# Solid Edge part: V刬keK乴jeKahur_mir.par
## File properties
Last saved by: Egon 815
Revision: 52
Accuracy: 0,990
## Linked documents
ljeKahur.par
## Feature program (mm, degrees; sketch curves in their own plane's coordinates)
part copy "CopiedPart_1"
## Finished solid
Body 1: solid body, 18 faces, 34 edges, 18 vertices.
  Faces by surface: plane 11, cone 3, cylinder 2, spline 2
  Edges by curve: line 14, circle 11, curve on surface 7, intersection 2
Bounding box of the edges (mm; curved faces can reach further): 2182.208 x 5485.690 x 2152.254, from (10802.6405, 23199.3222, 5032.5774) to (12984.8483, 28685.0118, 7184.8312).
Cylindrical faces by radius (mm): R125 x1, R1091.1039 x1
Conical faces (half-angle, radius in mm at the cone's reference point): 45 deg R1091.1039 x3
Planar faces by outward normal: +x 1, +y 4, +z 2, -x 1, -z 2, oblique 1
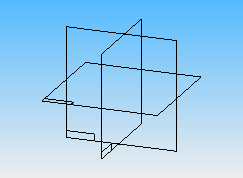
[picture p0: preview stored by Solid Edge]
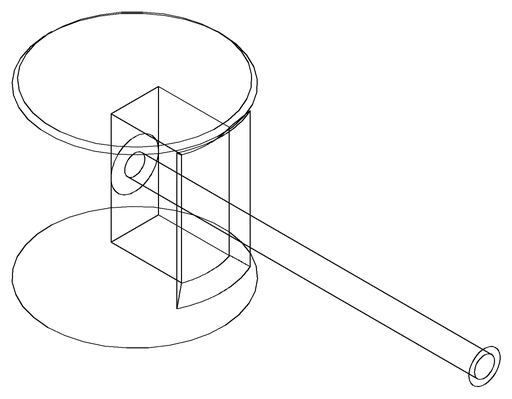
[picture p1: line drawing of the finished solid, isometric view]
